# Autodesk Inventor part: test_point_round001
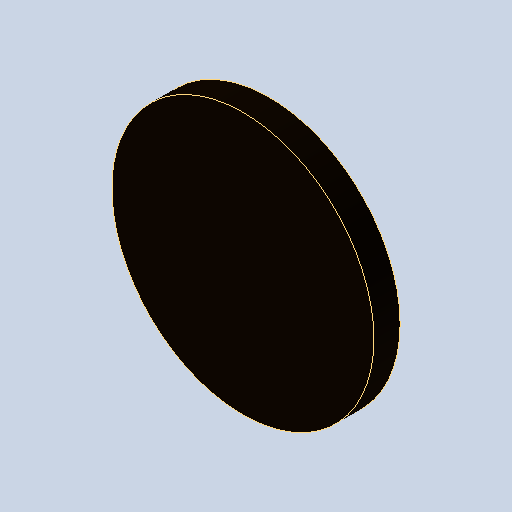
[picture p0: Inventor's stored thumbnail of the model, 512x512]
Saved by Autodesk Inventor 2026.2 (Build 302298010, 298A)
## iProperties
Created: 2026-10
Part Number: test_point_round001
Material: Générique
Document SubType Name: Modeling
Designer: mel
Density: 1 g/cm^3
Appearance: Par défaut
Author: mel
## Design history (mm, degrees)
feature "Base1"
node "Solide1"
